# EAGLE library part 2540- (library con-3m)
3M (TM) Pak 100 4-Wall Header Source: 3M
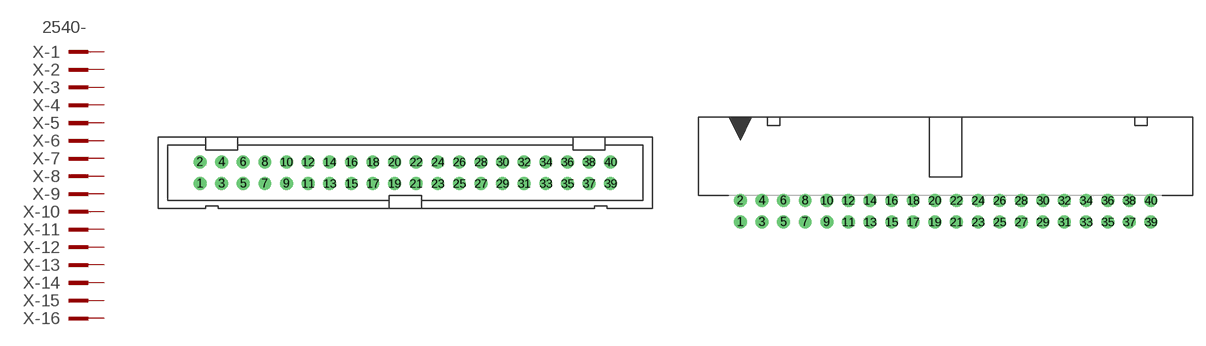
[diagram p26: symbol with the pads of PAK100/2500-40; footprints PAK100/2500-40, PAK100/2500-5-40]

Designator prefix X; gates -1=PINV -2=PIN -3=PIN -4=PIN -5=PIN -6=PIN -7=PIN -8=PIN -9=PIN -10=PIN -11=PIN -12=PIN -13=PIN -14=PIN -15=PIN -16=PIN -17=PIN -18=PIN -19=PIN -20=PIN -21=PIN -22=PIN -23=PIN -24=PIN -25=PIN -26=PIN -27=PIN -28=PIN -29=PIN -30=PIN -31=PIN -32=PIN -33=PIN -34=PIN -35=PIN -36=PIN -37=PIN -38=PIN -39=PIN -40=PIN

## 2540- (OC_FARNELL: unknown; OC_NEWARK: unknown)  [PAK100/2500-40]
1  -1:KL  pas
2  -2:KL  pas
3  -3:KL  pas
4  -4:KL  pas
5  -5:KL  pas
6  -6:KL  pas
7  -7:KL  pas
8  -8:KL  pas
9  -9:KL  pas
10  -10:KL  pas
11  -11:KL  pas
12  -12:KL  pas
13  -13:KL  pas
14  -14:KL  pas
15  -15:KL  pas
16  -16:KL  pas
17  -17:KL  pas
18  -18:KL  pas
19  -19:KL  pas
20  -20:KL  pas
21  -21:KL  pas
22  -22:KL  pas
23  -23:KL  pas
24  -24:KL  pas
25  -25:KL  pas
26  -26:KL  pas
27  -27:KL  pas
28  -28:KL  pas
29  -29:KL  pas
30  -30:KL  pas
31  -31:KL  pas
32  -32:KL  pas
33  -33:KL  pas
34  -34:KL  pas
35  -35:KL  pas
36  -36:KL  pas
37  -37:KL  pas
38  -38:KL  pas
39  -39:KL  pas
40  -40:KL  pas

## 2540-5 (OC_FARNELL: 9838414; OC_NEWARK: unknown)  [PAK100/2500-5-40]
Pads as for PAK100/2500-40

## Footprint PAK100/2500-40 (pad centres in mm)
3M (TM) Pak 100 4-Wall Header Straight Source: 3M
drill 1 pad 1.422 round: 1 -24.13,-1.27; 2 -24.13,1.27; 3 -21.59,-1.27; 4 -21.59,1.27; 5 -19.05,-1.27; 6 -19.05,1.27; 7 -16.51,-1.27; 8 -16.51,1.27; 9 -13.97,-1.27; 10 -13.97,1.27; 11 -11.43,-1.27; 12 -11.43,1.27; 13 -8.89,-1.27; 14 -8.89,1.27; 15 -6.35,-1.27; 16 -6.35,1.27; 17 -3.81,-1.27; 18 -3.81,1.27; 19 -1.27,-1.27; 20 -1.27,1.27; 21 1.27,-1.27; 22 1.27,1.27; 23 3.81,-1.27; 24 3.81,1.27; 25 6.35,-1.27; 26 6.35,1.27; 27 8.89,-1.27; 28 8.89,1.27; 29 11.43,-1.27; 30 11.43,1.27; 31 13.97,-1.27; 32 13.97,1.27; 33 16.51,-1.27; 34 16.51,1.27; 35 19.05,-1.27; 36 19.05,1.27; 37 21.59,-1.27; 38 21.59,1.27; 39 24.13,-1.27; 40 24.13,1.27

## Footprint PAK100/2500-5-40 (pad centres in mm)
3M (TM) Pak 100 4-Wall Header Right Angle Source: 3M
drill 1 pad 1.422 round: 1 -24.13,-1.27; 2 -24.13,1.27; 3 -21.59,-1.27; 4 -21.59,1.27; 5 -19.05,-1.27; 6 -19.05,1.27; 7 -16.51,-1.27; 8 -16.51,1.27; 9 -13.97,-1.27; 10 -13.97,1.27; 11 -11.43,-1.27; 12 -11.43,1.27; 13 -8.89,-1.27; 14 -8.89,1.27; 15 -6.35,-1.27; 16 -6.35,1.27; 17 -3.81,-1.27; 18 -3.81,1.27; 19 -1.27,-1.27; 20 -1.27,1.27; 21 1.27,-1.27; 22 1.27,1.27; 23 3.81,-1.27; 24 3.81,1.27; 25 6.35,-1.27; 26 6.35,1.27; 27 8.89,-1.27; 28 8.89,1.27; 29 11.43,-1.27; 30 11.43,1.27; 31 13.97,-1.27; 32 13.97,1.27; 33 16.51,-1.27; 34 16.51,1.27; 35 19.05,-1.27; 36 19.05,1.27; 37 21.59,-1.27; 38 21.59,1.27; 39 24.13,-1.27; 40 24.13,1.27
